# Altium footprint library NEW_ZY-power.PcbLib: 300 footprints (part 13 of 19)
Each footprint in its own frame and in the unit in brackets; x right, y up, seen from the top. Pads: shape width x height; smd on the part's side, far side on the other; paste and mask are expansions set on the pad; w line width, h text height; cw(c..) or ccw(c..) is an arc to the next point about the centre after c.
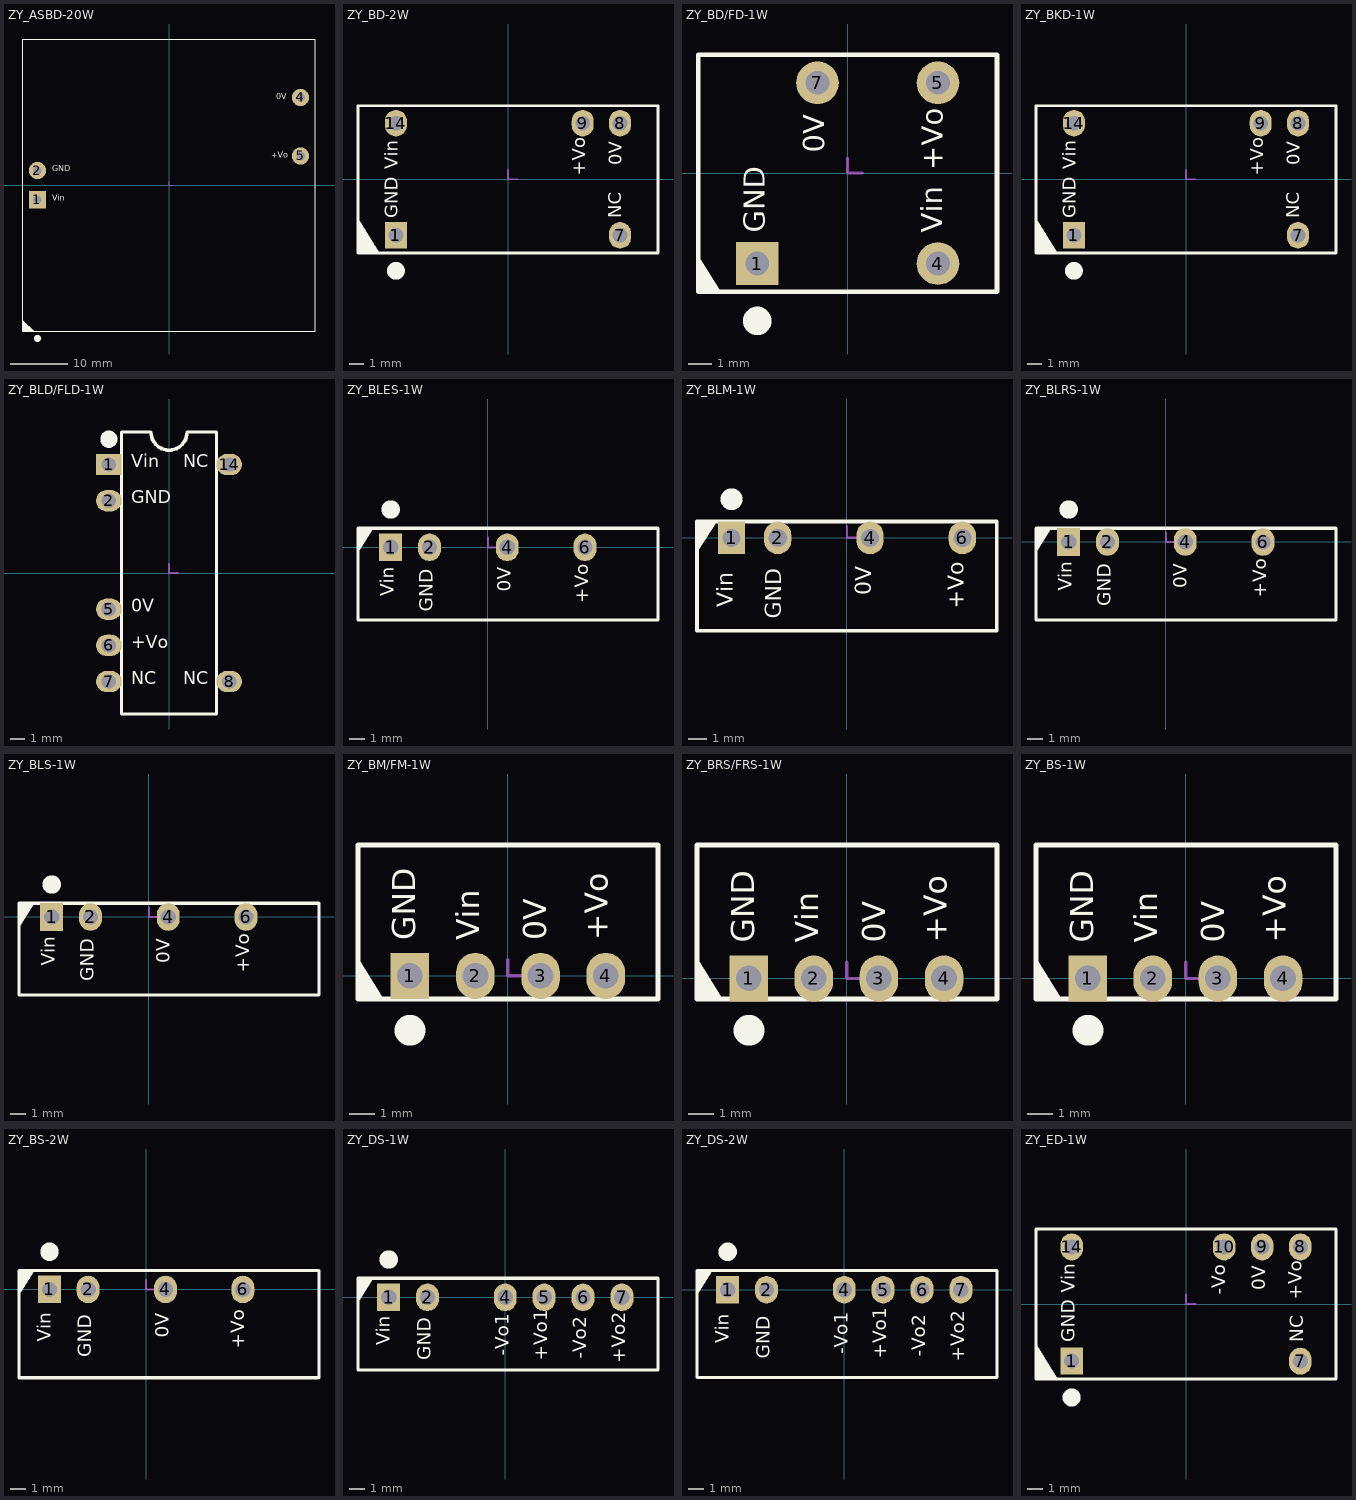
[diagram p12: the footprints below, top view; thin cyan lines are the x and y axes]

## ZY_ASBD-20W [mm]
height 12.8
pads (4):
  rect 3x3 hole 1.5: 1(-22.86,-2.54)
  round 3 hole 1.5: 2(-22.86,2.54) 4(22.86,15.24) 5(22.86,5.08)
Top Overlay:
  circle w1: c-22.86,-26.625 r0.1
  region: -25.4,-25.4 -23.425,-25.4 -25.4,-23.425
  lines w0.2: -25.4,-25.4 -25.4,25.4 25.4,25.4 25.4,-25.4 -25.4,-25.4
  text "GND" at -20.32,2.034 h1.78
  text "Vin" at -20.32,-3.046 h1.78
  text "0V" at 18.644,14.607 h1.78
  text "+Vo" at 17.78,4.447 h1.78
Mechanical 15:
  lines w0.127: 0,0.635 0,0 0.635,0

## ZY_BD-2W [mm]
height 8.1
pads (5):
  rect 1.5x1.8 hole 1: 1(-7.62,-3.81)
  oval 1.5x1.8 hole 1: 7(7.62,-3.81) 8(7.62,3.81) 9(5.08,3.81) 14(-7.62,3.81)
Top Overlay:
  circle w1: c-7.62,-6.225 r0.1
  region: -10.2,-2.67 -10.2,-5 -8.74,-5
  lines w0.2: -10.2,-5 10.2,-5 10.2,5 -10.2,5 -10.2,-5
  text "GND" at -7.188,-2.667 h1.52
  text "NC" at 8.001,-2.667 h1.52
  text "Vin" at -7.188,0.695 h1.52
  text "+Vo" at 5.563,0.227 h1.52
  text "0V" at 8.052,0.967 h1.52
Mechanical 15:
  lines w0.127: 0,0.635 0,0 0.635,0

## ZY_BD/FD-1W [mm] "定压输入隔离非稳压单输出"
height 7.7
pads (4):
  rect 1.8x1.8 hole 1: 1(-3.81,-3.81)
  round 1.8 hole 1: 4(3.81,-3.81) 5(3.81,3.81) 7(-1.27,3.81)
Top Overlay:
  circle w1: c-3.81,-6.229 r0.1
  region: -6.35,-3.418 -6.35,-5.004 -5.356,-5.004
  lines w0.2: -6.299,-5.004 6.301,-5.004 6.301,4.996 -6.299,4.996 -6.299,-5.004
  text "0V" at -0.686,0.864 h1.52
  text "+Vo" at 4.318,0.124 h1.52
  text "Vin" at 4.293,-2.515 h1.52
  text "GND" at -3.2,-2.516 h1.52
Mechanical 15:
  lines w0.127: 0,0.635 0,0 0.635,0

## ZY_BKD-1W [mm]
height 8.1
pads (5):
  rect 1.5x1.8 hole 1: 1(-7.62,-3.81)
  oval 1.5x1.8 hole 1: 7(7.62,-3.81) 8(7.62,3.81) 9(5.08,3.81) 14(-7.62,3.81)
Top Overlay:
  circle w1: c-7.62,-6.225 r0.1
  region: -10.2,-2.67 -10.2,-5 -8.74,-5
  lines w0.2: -10.2,-5 -10.2,5 10.2,5 10.2,-5 -10.2,-5
  text "0V" at 8.052,0.967 h1.52
  text "+Vo" at 5.563,0.227 h1.52
  text "Vin" at -7.188,0.695 h1.52
  text "NC" at 8.001,-2.667 h1.52
  text "GND" at -7.188,-2.667 h1.52
Mechanical 15:
  lines w0.127: 0,0.635 0,0 0.635,0

## ZY_BLD/FLD-1W [mm] "定压输入隔离非稳压单输出"
height 5.5
pads (7):
  rect 1.8x1.5 hole 1: 1(-4.225,7.62)
  oval 1.8x1.5 hole 1: 2(-4.225,5.08) 5(-4.225,-2.54) 6(-4.225,-5.08) 7(-4.225,-7.62) 8(4.225,-7.62) 14(4.225,7.62)
Top Overlay:
  circle w1: c-4.225,9.398 r0.1
  lines w0.2: -1.27,9.9 -3.336,9.9 -3.336,-9.9 3.344,-9.9 3.344,9.9 1.27,9.9
  lines w0.254: -1.27,9.9 ccw(c0,9.9) 0,8.63 ccw(c0,9.9) 1.27,9.9
  text "Vin" at -2.667,7.112 h1.52
  text "GND" at -2.668,4.572 h1.52
  text "+Vo" at -2.668,-5.588 h1.52
  text "0V" at -2.668,-3.048 h1.52
  text "NC" at -2.668,-8.128 h1.52
  text "NC" at 1.016,-8.128 h1.52
  text "NC" at 1.016,7.112 h1.52
Mechanical 15:
  lines w0.127: 0,0.635 0,0 0.635,0

## ZY_BLES-1W [mm]
height 10
pads (4):
  rect 1.5x1.8 hole 1: 1(-6.35,0)
  oval 1.5x1.8 hole 1: 2(-3.81,0) 4(1.27,0) 6(6.35,0)
Top Overlay:
  circle w1: c-6.35,2.475 r0.1
  region: -8.48,-0.336 -8.48,1.25 -7.486,1.25
  lines w0.2: -8.48,-4.75 -8.48,1.25 11.12,1.25 11.12,-4.75 -8.48,-4.75
  text "+Vo" at 6.858,-3.649 h1.52
  text "0V" at 1.803,-2.909 h1.52
  text "GND" at -3.302,-4.191 h1.52
  text "Vin" at -5.842,-3.181 h1.52
Mechanical 15:
  lines w0.127: 0,0.635 0,0 0.635,0

## ZY_BLM-1W [mm]
height 7.5
pads (4):
  rect 1.5x1.8 hole 1: 1(-6.35,0)
  oval 1.5x1.8 hole 1: 2(-3.81,0) 4(1.27,0) 6(6.35,0)
Top Overlay:
  circle w1: c-6.35,2.125 r0.1
  region: -8.169,-0.686 -8.169,0.9 -7.175,0.9
  lines w0.2: -8.25,-5.1 -8.25,0.9 8.25,0.9 8.25,-5.1 -8.25,-5.1
  text "Vin" at -5.969,-3.816 h1.52
  text "GND" at -3.302,-4.445 h1.52
  text "0V" at 1.651,-3.163 h1.52
  text "+Vo" at 6.731,-3.903 h1.52
Mechanical 15:
  lines w0.127: 0,0.635 0,0 0.635,0

## ZY_BLRS-1W [mm]
height 10
pads (4):
  rect 1.5x1.8 hole 1: 1(-6.35,0)
  oval 1.5x1.8 hole 1: 2(-3.81,0) 4(1.27,0) 6(6.35,0)
Top Overlay:
  circle w1: c-6.35,2.125 r0.1
  region: -8.48,-0.686 -8.48,0.9 -7.486,0.9
  lines w0.2: -8.48,-5.1 -8.48,0.9 11.12,0.9 11.12,-5.1 -8.48,-5.1
  text "+Vo" at 6.858,-3.649 h1.52
  text "0V" at 1.676,-3.036 h1.52
  text "GND" at -3.302,-4.191 h1.52
  text "Vin" at -5.842,-3.181 h1.52
Mechanical 15:
  lines w0.127: 0,0.635 0,0 0.635,0

## ZY_BLS-1W [mm] "定压输入隔离非稳压单输出"
height 10
pads (4):
  rect 1.5x1.8 hole 1: 1(-6.35,0)
  oval 1.5x1.8 hole 1: 2(-3.81,0) 4(1.27,0) 6(6.35,0)
Top Overlay:
  circle w1: c-6.35,2.125 r0.1
  region: -8.48,-0.686 -8.48,0.9 -7.486,0.9
  lines w0.2: -8.48,-5.1 -8.48,0.9 11.12,0.9 11.12,-5.1 -8.48,-5.1
  text "Vin" at -5.842,-3.181 h1.52
  text "GND" at -3.302,-4.191 h1.52
  text "0V" at 1.676,-3.036 h1.52
  text "+Vo" at 6.858,-3.649 h1.52
Mechanical 15:
  lines w0.127: 0,0.635 0,0 0.635,0

## ZY_BM/FM-1W [mm]
height 10
pads (4):
  rect 1.5x1.8 hole 1: 1(-3.823,0)
  oval 1.5x1.8 hole 1: 2(-1.257,0) 3(1.283,0) 4(3.823,0)
Top Overlay:
  circle w1: c-3.81,-2.125 r0.1
  region: -5.837,0.686 -5.837,-0.9 -4.844,-0.9
  lines w0.2: -5.837,-0.9 5.863,-0.9 5.863,5.1 -5.837,5.1 -5.837,-0.9
  text "GND" at -3.315,1.396 h1.52
  text "Vin" at -0.826,1.397 h1.52
  text "0V" at 1.791,1.396 h1.52
  text "+Vo" at 4.204,1.396 h1.52
Mechanical 15:
  lines w0.127: 0,0.635 0,0 0.635,0

## ZY_BRS/FRS-1W [mm]
height 10
pads (4):
  rect 1.5x1.8 hole 1: 1(-3.823,0)
  oval 1.5x1.8 hole 1: 2(-1.283,0) 3(1.257,0) 4(3.797,0)
Top Overlay:
  circle w1: c-3.81,-2.025 r0.1
  region: -5.837,0.786 -5.837,-0.8 -4.844,-0.8
  lines w0.2: -5.837,-0.8 5.863,-0.8 5.863,5.2 -5.837,5.2 -5.837,-0.8
  text "GND" at -3.315,1.396 h1.52
  text "Vin" at -0.826,1.397 h1.52
  text "0V" at 1.791,1.396 h1.52
  text "+Vo" at 4.204,1.396 h1.52
Mechanical 15:
  lines w0.127: 0,0.635 0,0 0.635,0

## ZY_BS-1W [mm] "定压输入隔离非稳压单输出"
height 10
pads (4):
  rect 1.5x1.8 hole 1: 1(-3.823,0)
  oval 1.5x1.8 hole 1: 2(-1.283,0) 3(1.257,0) 4(3.797,0)
Top Overlay:
  circle w1: c-3.81,-2.025 r0.1
  region: -5.837,0.786 -5.837,-0.8 -4.844,-0.8
  lines w0.2: -5.837,-0.8 5.863,-0.8 5.863,5.2 -5.837,5.2 -5.837,-0.8
  text "GND" at -3.315,1.396 h1.52
  text "Vin" at -0.826,1.397 h1.52
  text "0V" at 1.791,1.396 h1.52
  text "+Vo" at 4.204,1.396 h1.52
Mechanical 15:
  lines w0.127: 0,0.635 0,0 0.635,0

## ZY_BS-2W [mm] "定压输入隔离非稳压单输出"
height 10
pads (4):
  rect 1.5x1.8 hole 1: 1(-6.35,0)
  oval 1.5x1.8 hole 1: 2(-3.81,0) 4(1.27,0) 6(6.35,0)
Top Overlay:
  circle w1: c-6.35,2.475 r0.1
  region: -8.35,-0.348 -8.35,1.238 -7.356,1.238
  lines w0.2: -8.35,1.238 -8.35,-5.8 11.25,-5.8 ; -8.35,1.25 11.25,1.25 ; 11.35,-5.8 11.35,1.25
  text "Vin" at -5.969,-3.435 h1.52
  text "GND" at -3.302,-4.445 h1.52
  text "0V" at 1.778,-3.163 h1.52
  text "+Vo" at 6.731,-3.903 h1.52
Mechanical 15:
  lines w0.127: 0,0.635 0,0 0.635,0

## ZY_DS-1W [mm]
pads (6):
  rect 1.5x1.8 hole 1: 1(-7.62,0)
  oval 1.5x1.8 hole 1: 2(-5.08,0) 4(0,0) 5(2.54,0) 6(5.08,0) 7(7.62,0)
Top Overlay:
  circle w1: c-7.62,2.475 r0.1
  region: -9.62,-0.336 -9.62,1.25 -8.626,1.25
  lines w0.2: -9.62,-4.75 9.98,-4.75 9.98,1.25 -9.62,1.25 -9.62,-4.75
  text "-Vo1" at 0.508,-3.828 h1.52
  text "Vin" at -7.239,-3.113 h1.52
  text "GND" at -4.572,-4.123 h1.52
  text "+Vo1" at 3.048,-4.14 h1.52
  text "-Vo2" at 5.588,-4.006 h1.52
  text "+Vo2" at 8.128,-4.318 h1.52
Mechanical 15:
  lines w0.127: 0,0.635 0,0 0.635,0

## ZY_DS-2W [mm] "定压输入隔离非稳压双输出"
height 10
pads (6):
  rect 1.5x1.8 hole 1: 1(-7.62,0)
  oval 1.5x1.8 hole 1: 2(-5.08,0) 4(0,0) 5(2.54,0) 6(5.08,0) 7(7.62,0)
Top Overlay:
  circle w1: c-7.62,2.475 r0.1
  region: -9.62,-0.336 -9.62,1.25 -8.626,1.25
  lines w0.2: -9.62,-5.75 9.98,-5.75 9.98,1.25 -9.62,1.25 -9.62,-5.75
  text "-Vo1" at 0.508,-4.209 h1.52
  text "Vin" at -7.239,-3.494 h1.52
  text "GND" at -4.572,-4.504 h1.52
  text "+Vo1" at 3.048,-4.521 h1.52
  text "-Vo2" at 5.588,-4.387 h1.52
  text "+Vo2" at 8.128,-4.699 h1.52
Mechanical 15:
  lines w0.127: 0,0.635 0,0 0.635,0

## ZY_ED-1W [mm] "定压输入隔离非稳压正、负输出"
height 7
pads (6):
  rect 1.5x1.8 hole 1: 1(-7.62,-3.81)
  oval 1.5x1.8 hole 1: 7(7.62,-3.81) 8(7.62,3.81) 9(5.08,3.81) 10(2.54,3.81) 14(-7.62,3.81)
Top Overlay:
  circle w1: c-7.62,-6.225 r0.1
  region: -10,-2.67 -10,-5 -8.54,-5
  lines w0.2: -10,-5 10,-5 10,5 -10,5 -10,-5
  text "+Vo" at 8.001,0.294 h1.52
  text "0V" at 5.588,0.907 h1.52
  text "-Vo" at 2.921,0.606 h1.52
  text "Vin" at -7.112,0.762 h1.52
  text "NC" at 8.128,-2.54 h1.52
  text "GND" at -7.112,-2.54 h1.52
Mechanical 15:
  lines w0.127: 0,0.635 0,0 0.635,0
